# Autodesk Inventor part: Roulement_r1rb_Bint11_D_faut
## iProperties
Created: 2011-10
Part Number: Roulement_r1rb_Bint11_D_faut
Document SubType Name: Modeling
Designer: Bruno
Author: Bruno
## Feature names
1. Base1
